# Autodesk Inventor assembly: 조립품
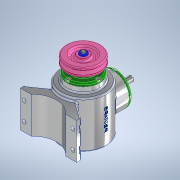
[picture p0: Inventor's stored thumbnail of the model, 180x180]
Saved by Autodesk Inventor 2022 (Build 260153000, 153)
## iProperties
Created: 2023-04
Part Number: 조립품
Document SubType Name: Assembly
Designer: Admin
Author: Admin
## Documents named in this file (17)
- C:\Users\Admin\Desktop\가마우지\조립품.iam
- C:\Users\Admin\Desktop\가마우지\본체.ipt
- C:\Users\Admin\Desktop\가마우지\커버.ipt
- C:\Users\Admin\Desktop\가마우지\베어링 6203.ipt
- C:\Users\Admin\Desktop\가마우지\오일실 17 x 32 x 8.ipt
- C:\Users\Admin\Desktop\가마우지\메인 축.ipt
- 메인 축.ipt
- C:\Users\Admin\Desktop\가마우지\키 5 x 5 x 14.ipt
- C:\Users\Admin\Desktop\가마우지\메인 베벨기어.ipt
- C:\Users\Admin\Desktop\가마우지\서브 축.ipt
- 서브 축.ipt
- C:\Users\Admin\Desktop\가마우지\키 4 x 4 x 14.ipt
- C:\Users\Admin\Desktop\가마우지\서브 베벨기어.ipt
- C:\Users\Admin\Desktop\가마우지\V-벨트풀리.ipt
- C:\Users\Admin\Desktop\가마우지\볼트 M4 x 10.ipt
- C:\Users\Admin\Desktop\가마우지\와셔 4 x 16.ipt
- C:\Users\Admin\Desktop\가마우지\육각볼트 M4 x 8.ipt
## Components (1 placed, 1 different names)
1. V-벨트풀리:1
